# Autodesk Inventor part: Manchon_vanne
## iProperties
Shininess: 64.0
Length Units: 11269
Angle Units: 11279
Time Units: 11290
Mass Units: 11283
Length Display Precision: 3
Angle Display Precision: 2
Compacted: True
Part Number: Manchon_vanne
Document SubType Name: Modeling
Created: 2008-02
Material: Acier inoxydable - 440C
Designer: Pascal
Density: 0.0
Volumn: 0.0
Area: 0.0
PropertySet Name: Model Information
Control State: 0
Master: False
Checked Out: False
DESIGNATION: pièce
Author: Pascal
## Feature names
1. Extrusion1
2. Chanfrein1 [Chamfer]
